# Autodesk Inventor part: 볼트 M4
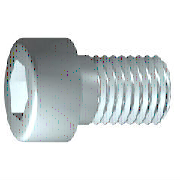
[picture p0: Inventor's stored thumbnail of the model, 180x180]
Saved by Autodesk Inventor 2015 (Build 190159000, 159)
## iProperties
IsCustomPart: 0
Created: 2018-09
Part Number: 볼트 M4
Material: 스테인리스강
Description: 6각머리 태핑 나사
Document SubType Name: Modeling
Standard: KS B 1003
Standards Organization: KS
Language: ko-KR
Size Designation: M 4 x 10
Categories: <MemberInstance><Categories><Category DisplayName="조임쇠" InternalName="e4da775c-781d-43d5-af7c-5136215cf5a6" Mnemonic="FSTN"><Category DisplayName="볼트" InternalN
Density: 8.08 g/cm^3
Appearance: 반광택
Mass: 2.09412 g
Surface Area: 3.0572 cm^2
Volume: 0.259174 cm^3
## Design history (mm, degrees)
sketch "스케치1"
  geometry: L1 (-1, 0)-(10, 0); L2 (10, 0)-(10, 2); L3 (10, 2)-(1.75, 2); L4 (1.75, 2)-(1.32, 2); L5 (1.32, 2)-(0, 2); L6 (0, 2)-(0, 3.5); L7 (0, 3.5)-(-4, 3.5); L8 (-4, 3.5)-(-4, 1.732); L9 (-4, 1.732)-(-2, 1.732); L10 (-2, 1.732)-(-1, 0); L11 (-6.8, 0)-(12.8, 0) reference; L12 (0, -0.7)-(0, 4.2) reference; L13 (1.75, 2)-(0, 2)
  constraints: 22 end point, 6 parallel, 2 collinear, 2 perpendicular, 1 horizontal, 1 point on line
  dimensions: "d1" = 8.25 distance from line of L3.end L2 (= GEL); "d2" = 0.42952 distance of L4.end L3.end (computed from GAL); "d3" = 4 distance between parallel lines of L8 L6 (= KOH); "d4" = 2 distance of L8.end L9.end (= INTI); "d5" = 60 deg angle of L10 L1; "d6" = 4 diameter of L3 L1 (= GD); "d7" = 4 diameter of L5 L1 (= BDM); "d8" = 3.4641 diameter of L9 L1 (= 1.1547 x SW); "d9" = 7 diameter of L7 L1 (= KOD); "d26" = 10 distance between parallel lines of L12 L2 (= NLG)
revolve "본체" sketch "스케치1" stored, may be unused: angle "d10" = 90 deg
sketch "스케치2"
  geometry: L1 (0, -4.9)-(0, 4.9) reference; L2 (-4.9, 0)-(4.9, 0) reference; L3 (1.732, 0)-(0.866, -1.5); L4 (0.866, -1.5)-(-0.866, -1.5); L5 (-0.866, -1.5)-(-1.732, 0); L6 (-1.732, 0)-(-0.866, 1.5); L7 (-0.866, 1.5)-(0.866, 1.5); L8 (0.866, 1.5)-(1.732, 0); 2 further points
  constraints: 12 end point, 1 coincident, 1 horizontal alignment, 1 point on line, 12 other
extrude "슬롯" join sketch "스케치2" stored distance "d11" = 10; taper "d12" = 0 deg
workplane "Work Plane1"
fillet "Fillet2" dims "d30" = 0.1 (= R)
body "Solid1"
fillet "모깎기1" dims "d17" = 0.4 (= RR)
feature "스레드" dims "d13" = 8.25 (= GEL), "d14" = 0
chamfer "모따기1" distance "d15" = 0.42941 (= -0.5 x SPD + 0.5 x GD); stored, may be unused: second distance "d16" = 0.42941 (= GUL), angle "d27" = 45 deg
other parameters: "GD" = 4 (= NND) [user parameter; used in 2 equation terms], "NLG" = 10 [user parameter; used in 1 equation term], "GEL" = 8.25 [user parameter; used in 2 equation terms], "KOD" = 7 [user parameter; used in 1 equation term], "KOH" = 4 [user parameter; used in 1 equation term], "INTI" = 2 [user parameter; used in 1 equation term], "GAL" = 0.42941 (= 0.61345 x PTC) [user parameter; used in 1 equation term], "GUL" = 0.42941 (= 0.61345 x PTC) [user parameter; used in 1 equation term], "BDM" = 4 (= NND) [user parameter; used in 1 equation term], "SW" = 3 [user parameter; used in 2 equation terms], "RR" = 0.4 [user parameter; used in 1 equation term], "SPD" = 3.14117 (= NND - 1.2269 x PTC) [user parameter; used in 1 equation term], "d19" = 0, "d28" = 0, "d29" = 0, "R" = 0.1 [user parameter; used in 1 equation term], "PHH" = 0.2 [user parameter], "GD1" = 3.14117 (= THREADDIA - 1.2269 x PTC) [user parameter], "THREADDIA" = 4 [user parameter; used in 1 equation term], "FAWI" = 45 deg [user parameter], "TPU" = 14.28571 (computed from PTC) [user parameter], "PTC" = 0.7 [user parameter; used in 5 equation terms], "NND" = 4 [user parameter; used in 3 equation terms], "TOA" = 30 deg [user parameter], "E0" = 3.465 (= 1.155 x SW) [user parameter]
